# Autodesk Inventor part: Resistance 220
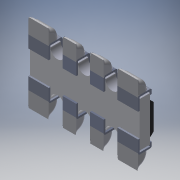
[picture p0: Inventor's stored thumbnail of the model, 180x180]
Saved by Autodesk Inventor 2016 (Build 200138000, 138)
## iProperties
Created: 2018-03
Part Number: Resistance 220
Material: Générique
Document SubType Name: Modeling
Designer: Bruno
Density: 1 g/cm^3
Appearance: Par défaut
Author: Bruno
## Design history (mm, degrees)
feature "Composite1"
body "Srf1"
